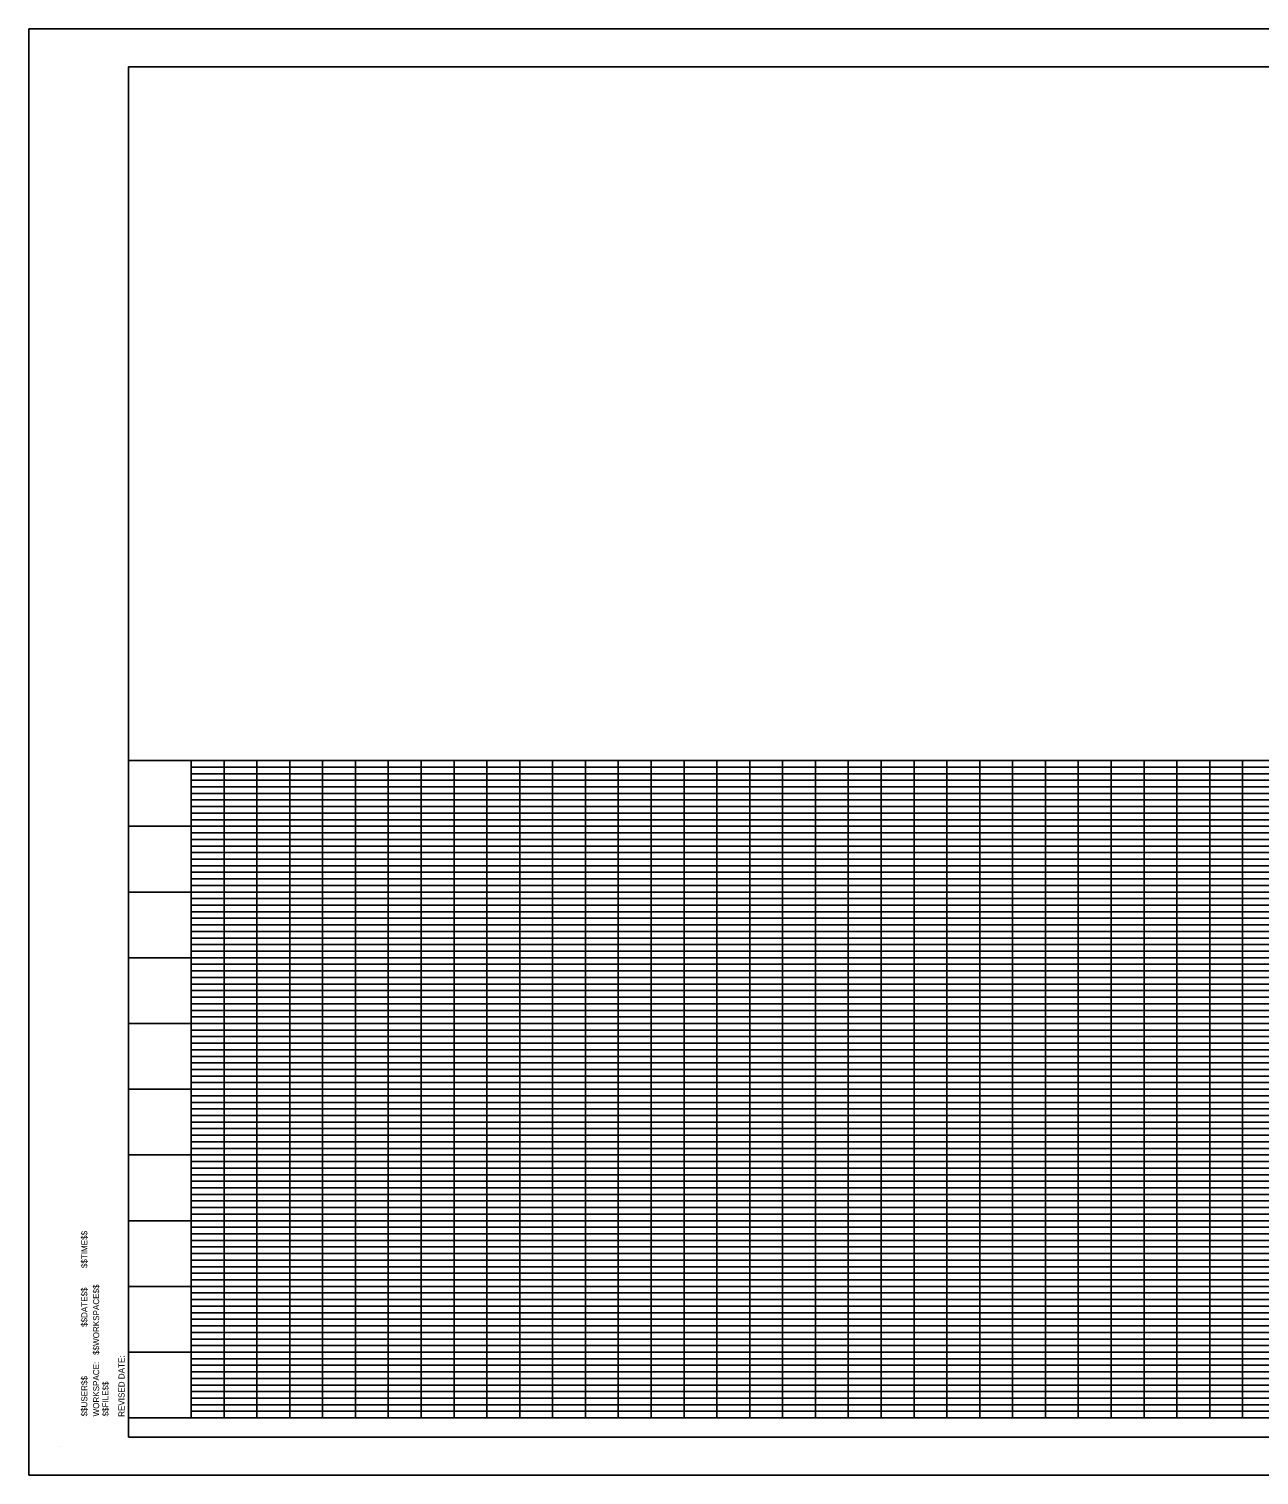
# Model space of a CAD drawing. Extents: x 759422 to 1467355, y 1662254 to 1691786.
# Drawn here: x 1465488 to 1466424, y 1690686 to 1691786 of the extents above; entities that cross this region are included whole.
import ezdxf

# ---------------------------------------------------------------- set-up
doc = ezdxf.new("R2010")
doc.units = 0
doc.layers.add('1', color=7, linetype='Continuous')

msp = doc.modelspace()

# ---------------------------------------------------------------- linework, layer by layer
at = {"layer": '1'}
for p, q in [((1465564.1, 1691757.4), (1467159.4, 1691757.4)), ((1465564.1, 1690715), (1465564.1, 1691757.4)), ((1465578.5, 1691757.4), (1466894.6, 1691757.4)), ((1467159.4, 1691229.7), (1465564.1, 1691229.7)), ((1465611.7, 1690729.7), (1465611.7, 1691229.7)), ((1465636.7, 1690729.7), (1465636.7, 1691229.7)), ((1465661.7, 1690729.7), (1465661.7, 1691229.7)), ((1465686.7, 1690729.7), (1465686.7, 1691229.7)), ((1465711.7, 1690729.7), (1465711.7, 1691229.7)), ((1465736.7, 1690729.7), (1465736.7, 1691229.7)), ((1465761.7, 1690729.7), (1465761.7, 1691229.7)), ((1465786.7, 1690729.7), (1465786.7, 1691229.7)), ((1465811.7, 1690729.7), (1465811.7, 1691229.7)), ((1465836.7, 1690729.7), (1465836.7, 1691229.7)), ((1465861.7, 1690729.7), (1465861.7, 1691229.7)), ((1465886.7, 1690729.7), (1465886.7, 1691229.7)), ((1465911.7, 1690729.7), (1465911.7, 1691229.7)), ((1465936.7, 1690729.7), (1465936.7, 1691229.7)), ((1465961.7, 1690729.7), (1465961.7, 1691229.7)), ((1465986.7, 1690729.7), (1465986.7, 1691229.7)), ((1466011.7, 1690729.7), (1466011.7, 1691229.7)), ((1466036.7, 1690729.7), (1466036.7, 1691229.7)), ((1466061.7, 1690729.7), (1466061.7, 1691229.7)), ((1466086.7, 1690729.7), (1466086.7, 1691229.7)), ((1466111.7, 1690729.7), (1466111.7, 1691229.7)), ((1466136.7, 1690729.7), (1466136.7, 1691229.7)), ((1466161.7, 1690729.7), (1466161.7, 1691229.7)), ((1466186.7, 1690729.7), (1466186.7, 1691229.7)), ((1466211.7, 1690729.7), (1466211.7, 1691229.7)), ((1466236.7, 1690729.7), (1466236.7, 1691229.7)), ((1466261.7, 1690729.7), (1466261.7, 1691229.7)), ((1466286.7, 1690729.7), (1466286.7, 1691229.7)), ((1466311.7, 1690729.7), (1466311.7, 1691229.7)), ((1466336.7, 1690729.7), (1466336.7, 1691229.7)), ((1466361.7, 1690729.7), (1466361.7, 1691229.7)), ((1466386.7, 1690729.7), (1466386.7, 1691229.7)), ((1466411.7, 1690729.7), (1466411.7, 1691229.7)), ((1467111.7, 1691224.7), (1465611.7, 1691224.7)), ((1467111.7, 1691219.7), (1465611.7, 1691219.7)), ((1467111.7, 1691214.7), (1465611.7, 1691214.7)), ((1467111.7, 1691209.7), (1465611.7, 1691209.7)), ((1467111.7, 1691204.7), (1465611.7, 1691204.7)), ((1467111.7, 1691199.7), (1465611.7, 1691199.7)), ((1467111.7, 1691194.7), (1465611.7, 1691194.7)), ((1467111.7, 1691189.7), (1465611.7, 1691189.7)), ((1467111.7, 1691184.7), (1465611.7, 1691184.7)), ((1467159.4, 1691179.7), (1465564.1, 1691179.7)), ((1467111.7, 1691174.7), (1465611.7, 1691174.7)), ((1467111.7, 1691169.7), (1465611.7, 1691169.7)), ((1467111.7, 1691164.7), (1465611.7, 1691164.7)), ((1467111.7, 1691159.7), (1465611.7, 1691159.7)), ((1467111.7, 1691154.7), (1465611.7, 1691154.7)), ((1467111.7, 1691149.7), (1465611.7, 1691149.7)), ((1467111.7, 1691144.7), (1465611.7, 1691144.7)), ((1467159.4, 1691129.7), (1465564.1, 1691129.7)), ((1467111.7, 1691139.7), (1465611.7, 1691139.7)), ((1467111.7, 1691134.7), (1465611.7, 1691134.7)), ((1467111.7, 1691124.7), (1465611.7, 1691124.7)), ((1467111.7, 1691119.7), (1465611.7, 1691119.7)), ((1467111.7, 1691114.7), (1465611.7, 1691114.7)), ((1467111.7, 1691109.7), (1465611.7, 1691109.7)), ((1467111.7, 1691104.7), (1465611.7, 1691104.7)), ((1467111.7, 1691099.7), (1465611.7, 1691099.7)), ((1467111.7, 1691094.7), (1465611.7, 1691094.7)), ((1467111.7, 1691089.7), (1465611.7, 1691089.7)), ((1467159.4, 1691079.7), (1465564.1, 1691079.7)), ((1467111.7, 1691084.7), (1465611.7, 1691084.7)), ((1467111.7, 1691074.7), (1465611.7, 1691074.7)), ((1467111.7, 1691069.7), (1465611.7, 1691069.7)), ((1467111.7, 1691064.7), (1465611.7, 1691064.7)), ((1467111.7, 1691059.7), (1465611.7, 1691059.7)), ((1467111.7, 1691054.7), (1465611.7, 1691054.7)), ((1467111.7, 1691049.7), (1465611.7, 1691049.7)), ((1467111.7, 1691044.7), (1465611.7, 1691044.7)), ((1467111.7, 1691039.7), (1465611.7, 1691039.7)), ((1467111.7, 1691034.7), (1465611.7, 1691034.7)), ((1467159.4, 1691029.7), (1465564.1, 1691029.7)), ((1467111.7, 1691024.7), (1465611.7, 1691024.7)), ((1467111.7, 1691019.7), (1465611.7, 1691019.7)), ((1467111.7, 1691014.7), (1465611.7, 1691014.7)), ((1467111.7, 1691009.7), (1465611.7, 1691009.7)), ((1467111.7, 1691004.7), (1465611.7, 1691004.7)), ((1467111.7, 1690999.7), (1465611.7, 1690999.7)), ((1467111.7, 1690994.7), (1465611.7, 1690994.7)), ((1467111.7, 1690989.7), (1465611.7, 1690989.7)), ((1467159.4, 1690979.7), (1465564.1, 1690979.7)), ((1467111.7, 1690984.7), (1465611.7, 1690984.7)), ((1467111.7, 1690974.7), (1465611.7, 1690974.7)), ((1467111.7, 1690969.7), (1465611.7, 1690969.7)), ((1467111.7, 1690964.7), (1465611.7, 1690964.7)), ((1467111.7, 1690959.7), (1465611.7, 1690959.7)), ((1467111.7, 1690954.7), (1465611.7, 1690954.7)), ((1467111.7, 1690949.7), (1465611.7, 1690949.7)), ((1467111.7, 1690944.7), (1465611.7, 1690944.7)), ((1467111.7, 1690939.7), (1465611.7, 1690939.7)), ((1467111.7, 1690934.7), (1465611.7, 1690934.7)), ((1467159.4, 1690929.7), (1465564.1, 1690929.7)), ((1467111.7, 1690924.7), (1465611.7, 1690924.7)), ((1467111.7, 1690919.7), (1465611.7, 1690919.7)), ((1467111.7, 1690914.7), (1465611.7, 1690914.7)), ((1467111.7, 1690909.7), (1465611.7, 1690909.7)), ((1467111.7, 1690904.7), (1465611.7, 1690904.7)), ((1467111.7, 1690899.7), (1465611.7, 1690899.7)), ((1467111.7, 1690894.7), (1465611.7, 1690894.7)), ((1467111.7, 1690889.7), (1465611.7, 1690889.7)), ((1467159.4, 1690879.7), (1465564.1, 1690879.7)), ((1467111.7, 1690884.7), (1465611.7, 1690884.7)), ((1467111.7, 1690874.7), (1465611.7, 1690874.7)), ((1467111.7, 1690869.7), (1465611.7, 1690869.7)), ((1467111.7, 1690864.7), (1465611.7, 1690864.7)), ((1467111.7, 1690859.7), (1465611.7, 1690859.7)), ((1467111.7, 1690854.7), (1465611.7, 1690854.7)), ((1467111.7, 1690849.7), (1465611.7, 1690849.7)), ((1467111.7, 1690844.7), (1465611.7, 1690844.7)), ((1467111.7, 1690839.7), (1465611.7, 1690839.7)), ((1467111.7, 1690834.7), (1465611.7, 1690834.7)), ((1467159.4, 1690829.7), (1465564.1, 1690829.7)), ((1467111.7, 1690824.7), (1465611.7, 1690824.7)), ((1467111.7, 1690819.7), (1465611.7, 1690819.7)), ((1467111.7, 1690814.7), (1465611.7, 1690814.7)), ((1467111.7, 1690809.7), (1465611.7, 1690809.7)), ((1467111.7, 1690804.7), (1465611.7, 1690804.7)), ((1467111.7, 1690799.7), (1465611.7, 1690799.7)), ((1467111.7, 1690794.7), (1465611.7, 1690794.7)), ((1467111.7, 1690789.7), (1465611.7, 1690789.7)), ((1467159.4, 1690779.7), (1465564.1, 1690779.7)), ((1467111.7, 1690784.7), (1465611.7, 1690784.7)), ((1467111.7, 1690774.7), (1465611.7, 1690774.7)), ((1467111.7, 1690769.7), (1465611.7, 1690769.7)), ((1467111.7, 1690764.7), (1465611.7, 1690764.7)), ((1467111.7, 1690759.7), (1465611.7, 1690759.7)), ((1467111.7, 1690754.7), (1465611.7, 1690754.7)), ((1467111.7, 1690749.7), (1465611.7, 1690749.7)), ((1467111.7, 1690744.7), (1465611.7, 1690744.7)), ((1467111.7, 1690739.7), (1465611.7, 1690739.7)), ((1467111.7, 1690734.7), (1465611.7, 1690734.7)), ((1467159.4, 1690729.7), (1465564.1, 1690729.7)), ((1467159.4, 1690715), (1465564.1, 1690715)), ((1465511.7, 1690707.6), (1465511.7, 1690707.6))]:
    msp.add_line(p, q, dxfattribs=at)
for points in [[(1467188.3, 1691786.2), (1465488.3, 1691786.2), (1465488.3, 1690686.2), (1467188.3, 1690686.2)], [(1465564.1, 1691229.7), (1465564.1, 1691757.4), (1466748.1, 1691757.4), (1466748.1, 1691708), (1466943.9, 1691708), (1466943.9, 1691693.4), (1467159.4, 1691693.4), (1467159.4, 1691229.7)], [(1465564.1, 1691757.4), (1466748.1, 1691757.4), (1466748.1, 1691708), (1466943.9, 1691708), (1466943.9, 1691693.4), (1467159.4, 1691693.4), (1467159.4, 1691229.7), (1465564.1, 1691229.7)], [(1465611.7, 1691229.7), (1467111.7, 1691229.7), (1467111.7, 1690729.7), (1465611.7, 1690729.7)], [(1465611.7, 1691229.7), (1467111.7, 1691229.7), (1467111.7, 1690729.7), (1465611.7, 1690729.7)]]:
    msp.add_lwpolyline(points, close=True, dxfattribs=at)

# ---------------------------------------------------------------- texts
for s, p in [('$$TIME$$', (1465532.7, 1690843.6)), ('$$DATE$$', (1465532.7, 1690798.9)), ('$$WORKSPACE$$', (1465541.7, 1690777.6)), ('WORKSPACE:', (1465541.7, 1690730.8)), ('REVISED DATE:', (1465561, 1690730.5)), ('$$USER$$', (1465532.7, 1690730.8)), ('$$FILE$$', (1465548.8, 1690730.8))]:
    msp.add_text(s, height=4.59, rotation=90, dxfattribs=at).set_placement(p)

doc.saveas('drawing.dxf')
